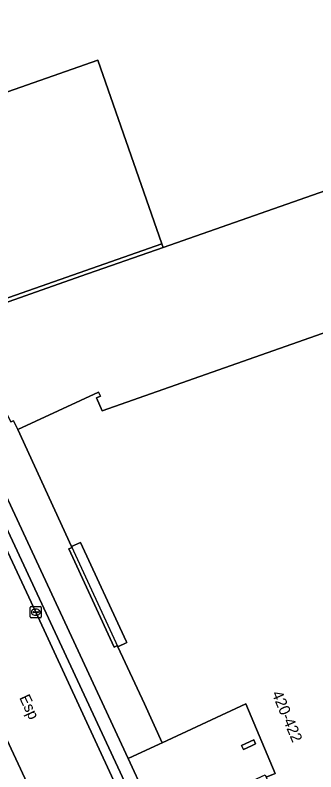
# Model space of a CAD drawing. Extents: x 161385 to 162589, y 388479 to 389756.
# Drawn here: x 162015.5 to 162042.8, y 388829.4 to 388897.9 of the extents above; entities that cross this region are included whole.
import ezdxf

# ---------------------------------------------------------------- set-up
doc = ezdxf.new("R2010")
doc.units = 0
for name, color, linetype in [('IMGEO_Berm_groen', 7, 'Continuous'), ('IMGEO_Erf', 7, 'Continuous'), ('IMGEO_Groenvoorziening', 7, 'Continuous'), ('IMGEO_Kolk', 7, 'Continuous'), ('IMGEO_Muur', 7, 'Continuous'), ('IMGEO_Openbare_ruimte_label', 7, 'Continuous'), ('IMGEO_Pand', 7, 'Continuous'), ('IMGEO_Pand_nummerreeks', 7, 'Continuous'), ('IMGEO_Pand_overbouw', 7, 'Continuous'), ('IMGEO_Rijbaan_lokaal_gesloten', 7, 'Continuous'), ('IMGEO_Voetpad_open', 7, 'Continuous')]:
    doc.layers.add(name, color=color, linetype=linetype)

msp = doc.modelspace()

# ---------------------------------------------------------------- linework, layer by layer
at = {"layer": 'IMGEO_Berm_groen'}
msp.add_lwpolyline([(162024.808, 388810.847), (162000, 388863.953), (161997.535, 388869.23), (161997.09, 388870.182), (161995.294, 388873.775), (161961.889, 388936.482)], dxfattribs=at)
msp.add_lwpolyline([(162011.813, 388857.716), (162011.069, 388857.378), (162017.391, 388843.863), (162025.739, 388825.856), (162028.29, 388820.387), (162029.065, 388820.712)], close=True, dxfattribs=at)
at = {"layer": 'IMGEO_Erf'}
for points in [[(162092.007, 388959.232), (162070.244, 388958.003), (162081.109, 388914.093), (162082.599, 388908.069), (162083.851, 388903.015), (162085.442, 388896.62), (162028.916, 388876.845), (162021.469, 388874.24), (162011.861, 388870.879), (162013.389, 388866.741)], [(162012.869, 388865.485), (162015.139, 388861.066), (162015.389, 388861.182), (162015.754, 388860.392), (162023.087, 388863.771), (162023.258, 388863.399), (162022.89, 388863.239), (162023.417, 388862.083), (162081.552, 388882.482)]]:
    msp.add_lwpolyline(points, dxfattribs=at)
msp.add_lwpolyline([(162022.998, 388893.779), (162003.194, 388886.856), (162006.457, 388880.63), (162006.058, 388880.421), (162008.488, 388875.805), (162008.886, 388876.016), (162011.488, 388871.116), (162028.802, 388877.172)], close=True, dxfattribs=at)
at = {"layer": 'IMGEO_Groenvoorziening'}
msp.add_lwpolyline([(162012.682, 388858.675), (162012.911, 388858.215), (162025.764, 388830.627), (162028.555, 388831.919), (162028.853, 388832.057), (162027.227, 388835.569), (162024.832, 388840.744), (162024.788, 388840.84), (162024.491, 388840.692), (162020.384, 388849.595), (162020.686, 388849.713), (162020.642, 388849.809), (162015.754, 388860.392), (162015.389, 388861.182), (162015.139, 388861.066)], dxfattribs=at)
msp.add_lwpolyline([(162020.384, 388849.595), (162024.491, 388840.692), (162024.788, 388840.84), (162024.832, 388840.744), (162025.64, 388841.124), (162025.587, 388841.238), (162021.451, 388850.176), (162020.642, 388849.809), (162020.686, 388849.713)], close=True, dxfattribs=at)
at = {"layer": 'IMGEO_Kolk'}
for p, q in [((162016.891, 388843.437), (162016.891, 388844.289)), ((162016.966, 388844.363), (162017.818, 388844.363)), ((162017.15, 388843.857), (162017.15, 388843.869)), ((162017.588, 388843.82), (162017.19, 388843.82)), ((162017.193, 388843.906), (162017.591, 388843.906)), ((162017.379, 388844.143), (162017.404, 388844.143)), ((162017.634, 388843.869), (162017.634, 388843.857)), ((162017.892, 388844.289), (162017.892, 388843.437)), ((162017.818, 388843.363), (162016.966, 388843.363)), ((162017.402, 388843.583), (162017.377, 388843.583))]:
    msp.add_line(p, q, dxfattribs=at)
for points in [[(162016.891, 388843.437), (162016.891, 388844.289)], [(162016.966, 388844.363), (162017.818, 388844.363)], [(162017.892, 388844.289), (162017.892, 388843.437)], [(162017.818, 388843.363), (162016.966, 388843.363)]]:
    msp.add_lwpolyline(points, dxfattribs=at)
for centre, radius, start, end in [((162016.968, 388844.287), 0.0765, 91.55205, 178.44795), ((162016.968, 388844.287), 0.0765, 91.55205, 178.44795), ((162017.19, 388843.866), 0.0403, 85.87752, 175.75265), ((162017.187, 388843.856), 0.0366, 178.93798, 274.71019), ((162017.591, 388843.863), 0.043, 264.86636, 352.45326), ((162017.595, 388843.868), 0.0386, 1.73085, 96.63898), ((162017.816, 388844.287), 0.0765, 1.55205, 88.44795), ((162017.816, 388844.287), 0.0765, 1.55205, 88.44795), ((162016.968, 388843.439), 0.0765, 181.55205, 268.44795), ((162016.968, 388843.439), 0.0765, 181.55205, 268.44795), ((162017.816, 388843.439), 0.0765, 271.55205, 358.44795), ((162017.816, 388843.439), 0.0765, 271.55205, 358.44795)]:
    msp.add_arc(centre, radius, start, end, dxfattribs=at)
for centre, major_axis, ratio, start_param, end_param in [((162017.378, 388843.863), (-0.387, 0.002), 0.722429, 4.712389, 7.853982), ((162017.403, 388843.863), (-0.39, 0.002), 0.717154, 1.570796, 4.712389)]:
    msp.add_ellipse(centre, major_axis=major_axis, ratio=ratio, start_param=start_param, end_param=end_param, dxfattribs=at)
at = {"layer": 'IMGEO_Muur'}
msp.add_lwpolyline([(162008.886, 388876.016), (162008.488, 388875.805), (162011.225, 388870.657), (162011.861, 388870.879), (162021.469, 388874.24), (162028.916, 388876.845), (162028.802, 388877.172), (162011.488, 388871.116)], close=True, dxfattribs=at)
at = {"layer": 'IMGEO_Pand'}
for points in [[(161997.381, 388898.862), (161998.275, 388897.186), (161997.728, 388896.895), (161997.634, 388897.072), (161997.395, 388896.945), (161997.547, 388896.655), (162002.763, 388886.705), (162003.194, 388886.856), (162022.998, 388893.779), (162028.802, 388877.172), (162028.916, 388876.845), (162085.442, 388896.62), (162083.851, 388903.015)], [(162096.812, 388887.735), (162081.552, 388882.482), (162023.417, 388862.083), (162022.89, 388863.239), (162023.258, 388863.399), (162023.087, 388863.771), (162015.754, 388860.392), (162020.642, 388849.809), (162021.451, 388850.176), (162025.587, 388841.238), (162025.64, 388841.124), (162024.832, 388840.744), (162027.227, 388835.569), (162028.853, 388832.057), (162036.403, 388835.564), (162039.082, 388829.266), (162038.244, 388828.934), (162044.342, 388815.75), (162045.228, 388813.835), (162048.347, 388807.09), (162093.508, 388826.06)]]:
    msp.add_lwpolyline(points, dxfattribs=at)
msp.add_lwpolyline([(162036.941, 388831.789), (162037.302, 388831.956), (162037.131, 388832.328), (162036.018, 388831.815), (162036.141, 388831.55), (162036.19, 388831.443)], close=True, dxfattribs=at)
at = {"layer": 'IMGEO_Pand_overbouw'}
msp.add_lwpolyline([(162024.832, 388840.744), (162025.64, 388841.124), (162025.587, 388841.238), (162021.451, 388850.176), (162020.642, 388849.809)], close=True, dxfattribs=at)
at = {"layer": 'IMGEO_Rijbaan_lokaal_gesloten'}
for points in [[(161961.889, 388936.482), (161995.294, 388873.775), (161997.09, 388870.182), (161997.535, 388869.23), (162000, 388863.953), (162024.808, 388810.847)], [(162025.739, 388825.856), (162017.391, 388843.863), (162011.069, 388857.378), (162008.771, 388862.289), (162007.587, 388864.793), (162003.94, 388872.507), (162003.111, 388874.261), (162002.202, 388876.053), (162000.316, 388879.659), (162000, 388880.264), (161999.51, 388881.201), (161992.639, 388894.058)]]:
    msp.add_lwpolyline(points, dxfattribs=at)
at = {"layer": 'IMGEO_Voetpad_open'}
for points in [[(162025.764, 388830.627), (162012.911, 388858.215), (162011.813, 388857.716), (162029.065, 388820.712), (162030.141, 388821.232), (162029.781, 388822.005), (162027.252, 388827.432)], [(162036.941, 388831.789), (162036.19, 388831.443), (162036.141, 388831.55), (162036.018, 388831.815), (162037.131, 388832.328), (162037.302, 388831.956)]]:
    msp.add_lwpolyline(points, close=True, dxfattribs=at)
msp.add_lwpolyline([(162034.138, 388823.544), (162032.692, 388826.647), (162038.151, 388829.138), (162038.244, 388828.934), (162039.082, 388829.266), (162036.403, 388835.564), (162028.853, 388832.057), (162028.555, 388831.919), (162025.764, 388830.627), (162027.252, 388827.432), (162030.042, 388828.735), (162033.185, 388822.003), (162033.654, 388822.215)], dxfattribs=at)

# ---------------------------------------------------------------- texts
at = {"layer": 'IMGEO_Openbare_ruimte_label'}
msp.add_text('Esp', height=1, rotation=295.02728, dxfattribs=at).set_placement((162015.874, 388836.137))
at = {"layer": 'IMGEO_Pand_nummerreeks'}
msp.add_text('420-422', height=1, rotation=293.0436, dxfattribs=at).set_placement((162038.74, 388836.507))

doc.saveas('drawing.dxf')
